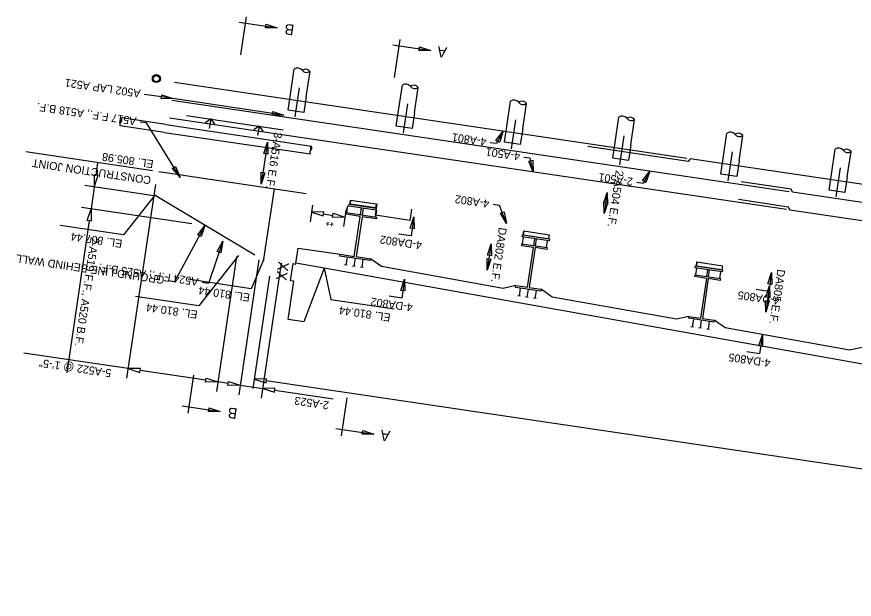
# Model space of a CAD drawing. Extents: x 1468952 to 1470054, y 573916 to 574214.
# Drawn here: x 1468962.4 to 1469014.8, y 574056.5 to 574092.9 of the extents above; entities that cross this region are included whole.
import ezdxf

# ---------------------------------------------------------------- set-up
doc = ezdxf.new("R2010")
doc.units = 0
for name, color, linetype in [('BR_P_Beam_Object', 7, 'Continuous'), ('BR_P_Beam_Stl_Det', 7, 'Continuous'), ('BR_P_Gen_Centerline', 7, 'Continuous'), ('BR_P_Gen_Phase_Construction', 7, 'Continuous'), ('BR_P_Sub_Centerline', 7, 'Continuous'), ('BR_P_Sub_Deep_Centerline', 7, 'Continuous'), ('BR_P_Sub_Foot_Centerline', 7, 'Continuous'), ('BR_P_Sub_Foot_Hidden', 7, 'Continuous'), ('BR_X_SV_Beam_Seat', 7, 'Continuous'), ('Default', 7, 'Continuous'), ('GE_P_CL_50', 7, 'Continuous'), ('GK_Cells', 7, 'Continuous'), ('PF_X_Ground_Line', 7, 'Continuous'), ('PV_X_EOP', 7, 'Continuous'), ('SV_X_Text_Elevation', 7, 'Continuous'), ('UT_X_Water', 7, 'Continuous')]:
    doc.layers.add(name, color=color, linetype=linetype)

# ---------------------------------------------------------------- blocks, each defined once
blk = doc.blocks.new('arrowOhio')
at = {"layer": 'Default'}
blk.add_lwpolyline([(0.00381, 0.000635), (0.00381, -0.000635), (0, 0)], close=True, dxfattribs=at)

msp = doc.modelspace()

# ---------------------------------------------------------------- linework, layer by layer
at = {"layer": 'BR_P_Beam_Object'}
for p, q in [((1468971.669, 574085.68), (1468980.77, 574084.333)), ((1468971.743, 574086.174), (1468980.843, 574084.827)), ((1468977.303, 574077.995), (1468971.084, 574081.728))]:
    msp.add_line(p, q, dxfattribs=at)
for centre, start, end in [((1468980.955, 574084.684), 127.976, 215.1816), ((1468980.695, 574084.723), 307.976, 35.1816), ((1468980.918, 574084.437), 127.976, 215.1816)]:
    msp.add_arc(centre, 0.181, start, end, dxfattribs=at)
at = {"layer": 'BR_P_Beam_Stl_Det'}
for p, q in [((1468976.329, 574092.572), (1468978.703, 574092.22)), ((1468976.432, 574090.535), (1468976.783, 574092.909)), ((1468986.025, 574089.115), (1468986.377, 574091.489)), ((1468985.922, 574091.152), (1468988.296, 574090.8)), ((1469004.297, 574084.051), (1468972.298, 574088.788)), ((1469010.688, 574081.967), (1468972.133, 574087.675)), ((1469010.523, 574080.854), (1468971.968, 574086.562)), ((1468973.468, 574070.513), (1468973.116, 574068.139)), ((1468983.061, 574069.093), (1468982.709, 574066.719)), ((1468972.779, 574068.593), (1468975.153, 574068.242)), ((1468982.372, 574067.173), (1468984.746, 574066.821))]:
    msp.add_line(p, q, dxfattribs=at)
for points in [[(1469030.229, 574080.212), (1469004.495, 574084.021), (1469004.371, 574083.865), (1468998.106, 574084.792)], [(1469046.308, 574076.694), (1469010.886, 574081.938), (1469010.812, 574082.124), (1469007.68, 574082.588)], [(1469046.144, 574075.581), (1469010.721, 574080.825), (1469010.648, 574081.011), (1469007.515, 574081.475)]]:
    msp.add_lwpolyline(points, dxfattribs=at)
at = {"layer": 'BR_P_Gen_Centerline'}
for p, q in [((1468971.743, 574086.174), (1468968.973, 574086.585)), ((1468971.669, 574085.68), (1468968.9, 574086.09))]:
    msp.add_line(p, q, dxfattribs=at)
for radius in [0.25, 0.2]:
    msp.add_circle((1468971.156, 574089.041), radius, dxfattribs=at)
for centre, start, end in [((1468969.048, 574086.194), 127.976, 215.1816), ((1468969.084, 574086.442), 127.976, 215.1816), ((1468968.825, 574086.48), 307.976, 35.1816)]:
    msp.add_arc(centre, 0.181, start, end, dxfattribs=at)
at = {"layer": 'BR_P_Gen_Phase_Construction'}
for p, q in [((1468979.531, 574088.054), (1468979.766, 574089.637)), ((1468980.52, 574087.908), (1468980.755, 574089.49)), ((1468986.291, 574087.053), (1468986.525, 574088.636)), ((1468987.28, 574086.907), (1468987.514, 574088.49)), ((1468993.051, 574086.053), (1468993.285, 574087.635)), ((1468994.04, 574085.906), (1468994.274, 574087.489)), ((1468999.81, 574085.052), (1469000.044, 574086.635)), ((1469000.799, 574084.905), (1469001.034, 574086.488)), ((1469006.57, 574084.051), (1469006.804, 574085.634)), ((1469007.559, 574083.905), (1469007.793, 574085.487)), ((1469013.329, 574083.05), (1469013.564, 574084.633)), ((1469014.319, 574082.904), (1469014.553, 574084.487))]:
    msp.add_line(p, q, dxfattribs=at)
for centre, start, end in [((1468979.974, 574089.341), 37.976, 125.1816), ((1468980.469, 574089.267), 37.976, 125.1816), ((1468980.546, 574089.787), 217.976, 305.1816), ((1468986.734, 574088.34), 37.976, 125.1816), ((1468987.229, 574088.267), 37.976, 125.1816), ((1468987.306, 574088.786), 217.976, 305.1816), ((1468993.494, 574087.339), 37.976, 125.1816), ((1468993.988, 574087.266), 37.976, 125.1816), ((1468994.065, 574087.785), 217.976, 305.1816), ((1469000.253, 574086.338), 37.976, 125.1816), ((1469000.748, 574086.265), 37.976, 125.1816), ((1469000.825, 574086.784), 217.976, 305.1816), ((1469007.013, 574085.338), 37.976, 125.1816), ((1469007.508, 574085.264), 37.976, 125.1816), ((1469007.584, 574085.784), 217.976, 305.1816), ((1469013.773, 574084.337), 37.976, 125.1816), ((1469014.267, 574084.264), 37.976, 125.1816), ((1469014.344, 574084.783), 217.976, 305.1816)]:
    msp.add_arc(centre, 0.362, start, end, dxfattribs=at)
at = {"layer": 'BR_P_Sub_Centerline'}
for p, q in [((1468979.385, 574087.065), (1468979.531, 574088.054)), ((1468980.52, 574087.908), (1468980.374, 574086.918)), ((1468980.374, 574086.918), (1468979.385, 574087.065)), ((1468986.144, 574086.064), (1468986.291, 574087.053)), ((1468987.28, 574086.907), (1468987.134, 574085.918)), ((1468987.134, 574085.918), (1468986.144, 574086.064)), ((1468992.904, 574085.063), (1468993.051, 574086.053)), ((1468994.04, 574085.906), (1468993.893, 574084.917)), ((1468993.893, 574084.917), (1468992.904, 574085.063)), ((1468999.664, 574084.063), (1468999.81, 574085.052)), ((1469000.799, 574084.905), (1469000.653, 574083.916)), ((1469000.653, 574083.916), (1468999.664, 574084.063)), ((1469006.423, 574083.062), (1469006.57, 574084.051)), ((1469007.559, 574083.905), (1469007.413, 574082.915)), ((1469007.413, 574082.915), (1469006.423, 574083.062)), ((1469013.183, 574082.061), (1469013.329, 574083.05)), ((1469014.319, 574082.904), (1469014.172, 574081.915)), ((1469014.172, 574081.915), (1469013.183, 574082.061))]:
    msp.add_line(p, q, dxfattribs=at)
at = {"layer": 'BR_P_Sub_Deep_Centerline'}
msp.add_line((1468977.874, 574077.746), (1468978.527, 574082.158), dxfattribs=at)
at = {"layer": 'BR_P_Sub_Foot_Centerline'}
for p, q in [((1468983.062, 574080.665), (1468983.124, 574081.087)), ((1468983.909, 574080.539), (1468983.972, 574080.962)), ((1468984.028, 574080.522), (1468984.091, 574080.944)), ((1468984.876, 574080.396), (1468984.938, 574080.819)), ((1468994.039, 574078.706), (1468994.102, 574079.129)), ((1468994.736, 574078.603), (1468994.799, 574079.025)), ((1468994.835, 574078.588), (1468994.898, 574079.011)), ((1468995.532, 574078.485), (1468995.595, 574078.908)), ((1469004.856, 574076.771), (1469004.919, 574077.194)), ((1469005.553, 574076.668), (1469005.616, 574077.09)), ((1469005.652, 574076.653), (1469005.715, 574077.076)), ((1469006.349, 574076.55), (1469006.412, 574076.973))]:
    msp.add_line(p, q, dxfattribs=at)
at = {"layer": 'BR_P_Sub_Foot_Hidden'}
msp.add_line((1468981.648, 574077.187), (1468979.871, 574077.508), dxfattribs=at)
at = {"layer": 'BR_X_SV_Beam_Seat'}
for p, q in [((1468973.039, 574086.741), (1468979.083, 574085.846)), ((1468974.55, 574086.517), (1468974.229, 574086.279)), ((1468974.55, 574086.517), (1468974.463, 574085.923)), ((1468974.55, 574086.517), (1468974.789, 574086.196)), ((1468977.572, 574086.07), (1468977.251, 574085.831)), ((1468977.572, 574086.07), (1468977.485, 574085.476)), ((1468977.572, 574086.07), (1468977.811, 574085.748)), ((1468970.91, 574083.285), (1468962.997, 574084.457))]:
    msp.add_line(p, q, dxfattribs=at)
msp.add_lwpolyline([(1468987.091, 574080.89), (1468986.986, 574080.179), (1468984.843, 574080.496), (1468984.948, 574081.207)], dxfattribs=at)
at = {"layer": 'GE_P_CL_50'}
for p, q in [((1468983.188, 574081.078), (1468983.206, 574081.202)), ((1468984.875, 574080.828), (1468983.188, 574081.078)), ((1468983.206, 574081.202), (1468984.893, 574080.952)), ((1468983.294, 574081.452), (1468983.256, 574081.194)), ((1468984.882, 574081.217), (1468984.843, 574080.959)), ((1468984.893, 574080.952), (1468984.875, 574080.828)), ((1468994.111, 574079.517), (1468994.073, 574079.259)), ((1468994.005, 574079.143), (1468994.023, 574079.267)), ((1468995.692, 574078.893), (1468994.005, 574079.143)), ((1468994.023, 574079.267), (1468995.71, 574079.017)), ((1468995.699, 574079.282), (1468995.66, 574079.024)), ((1468995.71, 574079.017), (1468995.692, 574078.893)), ((1469004.822, 574077.208), (1469004.84, 574077.332)), ((1469004.84, 574077.332), (1469006.527, 574077.082)), ((1469004.928, 574077.582), (1469004.89, 574077.324)), ((1469006.516, 574077.347), (1469006.477, 574077.089)), ((1469006.509, 574076.958), (1469004.822, 574077.208)), ((1469006.527, 574077.082), (1469006.509, 574076.958))]:
    msp.add_line(p, q, dxfattribs=at)
for points in [[(1468984.882, 574081.217), (1468984.843, 574080.959), (1468983.256, 574081.194), (1468983.294, 574081.452)], [(1468995.699, 574079.282), (1468995.66, 574079.024), (1468994.073, 574079.259), (1468994.111, 574079.517)], [(1469006.516, 574077.347), (1469006.477, 574077.089), (1469004.89, 574077.324), (1469004.928, 574077.582)]]:
    msp.add_lwpolyline(points, close=True, dxfattribs=at)
at = {"layer": 'GK_Cells'}
for p, q in [((1468983.004, 574080.558), (1468983.021, 574080.671)), ((1468983.892, 574080.426), (1468983.004, 574080.558)), ((1468983.021, 574080.671), (1468984.917, 574080.39)), ((1468983.523, 574077.932), (1468983.892, 574080.426)), ((1468984.012, 574080.408), (1468983.643, 574077.915)), ((1468984.9, 574080.277), (1468984.012, 574080.408)), ((1468984.917, 574080.39), (1468984.9, 574080.277)), ((1468993.981, 574078.599), (1468993.998, 574078.712)), ((1468994.719, 574078.49), (1468993.981, 574078.599)), ((1468993.998, 574078.712), (1468995.573, 574078.479)), ((1468994.35, 574075.996), (1468994.719, 574078.49)), ((1468994.819, 574078.475), (1468994.449, 574075.981)), ((1468995.557, 574078.366), (1468994.819, 574078.475)), ((1468995.573, 574078.479), (1468995.557, 574078.366)), ((1468982.618, 574077.951), (1468982.635, 574078.064)), ((1468984.514, 574077.67), (1468982.618, 574077.951)), ((1468982.635, 574078.064), (1468983.523, 574077.932)), ((1468983.071, 574077.884), (1468982.998, 574077.389)), ((1468983.566, 574077.81), (1468983.493, 574077.316)), ((1468983.643, 574077.915), (1468984.531, 574077.783)), ((1468983.081, 574077.377), (1468982.916, 574077.401)), ((1468983.575, 574077.303), (1468983.41, 574077.328)), ((1468984.061, 574077.737), (1468983.987, 574077.242)), ((1468984.531, 574077.783), (1468984.514, 574077.67)), ((1468984.07, 574077.23), (1468983.905, 574077.255)), ((1469004.798, 574076.664), (1469004.815, 574076.777)), ((1469004.815, 574076.777), (1469006.39, 574076.544)), ((1469005.536, 574076.555), (1469004.798, 574076.664)), ((1469005.167, 574074.061), (1469005.536, 574076.555)), ((1469005.636, 574076.54), (1469005.266, 574074.046)), ((1469006.374, 574076.431), (1469005.636, 574076.54)), ((1469006.39, 574076.544), (1469006.374, 574076.431)), ((1468993.595, 574075.992), (1468993.612, 574076.105)), ((1468995.171, 574075.759), (1468993.595, 574075.992)), ((1468993.612, 574076.105), (1468994.35, 574075.996)), ((1468993.888, 574075.948), (1468993.815, 574075.454)), ((1468994.383, 574075.875), (1468994.31, 574075.381)), ((1468994.449, 574075.981), (1468995.187, 574075.872)), ((1468994.878, 574075.802), (1468994.804, 574075.307)), ((1468995.187, 574075.872), (1468995.171, 574075.759)), ((1468993.898, 574075.442), (1468993.733, 574075.466)), ((1468994.392, 574075.368), (1468994.227, 574075.393)), ((1468994.887, 574075.295), (1468994.722, 574075.32)), ((1469004.412, 574074.057), (1469004.429, 574074.17)), ((1469004.429, 574074.17), (1469005.167, 574074.061)), ((1469005.988, 574073.824), (1469004.412, 574074.057)), ((1469004.705, 574074.013), (1469004.632, 574073.519)), ((1469005.2, 574073.94), (1469005.127, 574073.446)), ((1469005.266, 574074.046), (1469006.004, 574073.937)), ((1469005.695, 574073.867), (1469005.621, 574073.372)), ((1469006.004, 574073.937), (1469005.988, 574073.824)), ((1469004.715, 574073.507), (1469004.55, 574073.531)), ((1469005.209, 574073.433), (1469005.044, 574073.458)), ((1469005.704, 574073.36), (1469005.539, 574073.385))]:
    msp.add_line(p, q, dxfattribs=at)
at = {"layer": 'PF_X_Ground_Line'}
for p, q in [((1468979.871, 574077.508), (1468980.011, 574078.452)), ((1468980.011, 574078.452), (1468982.795, 574078.04)), ((1468979.539, 574076.404), (1468979.698, 574077.476)), ((1468979.698, 574077.476), (1468979.862, 574077.451)), ((1468981.648, 574077.187), (1468980.376, 574073.837)), ((1468981.648, 574077.187), (1468981.648, 574077.187)), ((1468981.648, 574077.187), (1468981.648, 574077.187)), ((1469026.696, 574069.14), (1468981.648, 574077.187)), ((1468979.383, 574073.984), (1468979.737, 574076.375)), ((1468979.737, 574076.375), (1468979.539, 574076.404)), ((1468980.376, 574073.837), (1468979.383, 574073.984))]:
    msp.add_line(p, q, dxfattribs=at)
for points in [[(1468993.612, 574076.105), (1468992.828, 574075.93), (1468985.216, 574077.29), (1468984.531, 574077.783)], [(1469004.429, 574074.17), (1469003.646, 574073.998), (1468995.874, 574075.386), (1468995.187, 574075.872)], [(1469015.246, 574072.235), (1469014.463, 574072.066), (1469006.691, 574073.454), (1469006.004, 574073.937)]]:
    msp.add_lwpolyline(points, dxfattribs=at)
at = {"layer": 'PV_X_EOP'}
msp.add_line((1468971.306, 574083.227), (1468980.516, 574081.863), dxfattribs=at)
at = {"layer": 'SV_X_Text_Elevation'}
for p, q in [((1468971.195, 574087.94), (1468970.404, 574088.057)), ((1468972.193, 574087.793), (1468971.195, 574087.94)), ((1468972.193, 574087.793), (1468972.193, 574087.793)), ((1468979.13, 574086.766), (1468972.193, 574087.793)), ((1468970.539, 574086.269), (1468970.143, 574086.328)), ((1468972.634, 574082.862), (1468970.539, 574086.269)), ((1468992.826, 574085.749), (1468992.407, 574084.975)), ((1468978.099, 574085.065), (1468977.711, 574082.447)), ((1468992.407, 574084.975), (1468992.011, 574085.034)), ((1468994.515, 574084.06), (1468994.12, 574084.119)), ((1468967.389, 574083.016), (1468967.501, 574083.768)), ((1468994.692, 574083.198), (1468994.515, 574084.06)), ((1469001.981, 574083.256), (1469001.562, 574082.482)), ((1469001.562, 574082.482), (1469001.166, 574082.541)), ((1468970.997, 574081.713), (1468966.684, 574082.352)), ((1468967.278, 574082.264), (1468967.076, 574080.903)), ((1468971.094, 574082.427), (1468969.301, 574070.321)), ((1468971.092, 574081.782), (1468969.104, 574079.275)), ((1468999.326, 574081.922), (1468999.132, 574080.613)), ((1468973.38, 574079.97), (1468966.483, 574080.991)), ((1468980.911, 574081.123), (1468980.76, 574080.099)), ((1468992.59, 574081.104), (1468992.194, 574081.163)), ((1468993.031, 574079.988), (1468992.59, 574081.104)), ((1468981.599, 574080.581), (1468982.179, 574080.495)), ((1468983.008, 574080.902), (1468982.843, 574079.79)), ((1468966.965, 574080.151), (1468965.56, 574070.66)), ((1468987.241, 574080.393), (1468987.065, 574079.206)), ((1468969.104, 574079.275), (1468965.147, 574079.861)), ((1468974.193, 574079.862), (1468972.29, 574076.344)), ((1468975.301, 574078.886), (1468974.417, 574076.229)), ((1468987.065, 574079.206), (1468986.274, 574079.323)), ((1468992.073, 574078.713), (1468991.828, 574077.058)), ((1468976.289, 574077.98), (1468973.804, 574074.846)), ((1468976.156, 574077.926), (1468974.907, 574069.491)), ((1468977.557, 574077.718), (1468976.308, 574069.284)), ((1468977.874, 574077.746), (1468977.079, 574075.91)), ((1468978.958, 574077.511), (1468977.71, 574069.076)), ((1468981.648, 574077.187), (1468982.05, 574075.228)), ((1469009.588, 574076.921), (1469009.413, 574075.734)), ((1468972.29, 574076.344), (1468971.894, 574076.402)), ((1468977.079, 574075.91), (1468973.122, 574076.496)), ((1468974.417, 574076.229), (1468974.021, 574076.288)), ((1468978.226, 574076.7), (1468977.186, 574069.669)), ((1468986.665, 574076.507), (1468986.49, 574075.32)), ((1469009.413, 574075.734), (1469008.621, 574075.851)), ((1469009.466, 574076.094), (1469009.221, 574074.439)), ((1468973.804, 574074.846), (1468969.847, 574075.432)), ((1468982.05, 574075.228), (1468986.007, 574074.642)), ((1468986.49, 574075.32), (1468985.698, 574075.437)), ((1469009.013, 574073.035), (1469008.837, 574071.848)), ((1468969.389, 574070.915), (1468962.882, 574071.878)), ((1469008.837, 574071.848), (1469008.046, 574071.965)), ((1468974.243, 574070.196), (1468970.141, 574070.803)), ((1468975.644, 574069.989), (1468974.893, 574070.1)), ((1469070.259, 574056.497), (1468978.025, 574070.152)), ((1468976.396, 574069.877), (1468977.798, 574069.67)), ((1468978.549, 574069.559), (1468982.202, 574069.018))]:
    msp.add_line(p, q, dxfattribs=at)
for points in [[(1468967.515, 574082.997), (1468967.264, 574083.034), (1468967.278, 574082.264)], [(1468967.09, 574080.133), (1468966.84, 574080.17), (1468967.076, 574080.903)], [(1468981.581, 574080.456), (1468981.618, 574080.706), (1468980.848, 574080.692)], [(1468982.161, 574080.37), (1468982.198, 574080.621), (1468982.931, 574080.384)], [(1468970.123, 574070.678), (1468970.16, 574070.929), (1468969.389, 574070.915)], [(1468974.224, 574070.071), (1468974.262, 574070.321), (1468974.995, 574070.085)], [(1468975.626, 574069.863), (1468975.663, 574070.114), (1468976.396, 574069.877)], [(1468978.007, 574070.026), (1468978.044, 574070.277), (1468977.273, 574070.263)], [(1468978.531, 574069.433), (1468978.568, 574069.684), (1468977.798, 574069.67)]]:
    msp.add_lwpolyline(points, close=True, dxfattribs=at)
at = {"layer": 'UT_X_Water'}
for p, q in [((1468979.831, 574086.662), (1468980.099, 574088.475)), ((1468986.59, 574085.661), (1468986.859, 574087.475)), ((1468993.35, 574084.66), (1468993.618, 574086.474)), ((1469000.11, 574083.66), (1469000.378, 574085.473)), ((1469006.869, 574082.659), (1469007.138, 574084.473)), ((1469013.629, 574081.658), (1469013.897, 574083.472))]:
    msp.add_line(p, q, dxfattribs=at)

# ---------------------------------------------------------------- block references
at = {"layer": 'BR_P_Beam_Stl_Det', "xscale": 188.97600000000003, "yscale": 188.97599999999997, "rotation": 171.57876932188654}
for p in [(1468978.703, 574092.22), (1468988.296, 574090.8), (1468975.153, 574068.242), (1468984.746, 574066.821)]:
    msp.add_blockref('arrowOhio', p, dxfattribs=at)
at = {"layer": 'SV_X_Text_Elevation'}
for p, xscale, yscale, rotation in [((1468972.193, 574087.793), 191.49568000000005, 191.49568, 171.57876932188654), ((1468979.13, 574086.766), 191.49568000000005, 191.49568, 171.57876932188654), ((1468992.826, 574085.749), 191.49567999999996, 191.49568, -118.42123067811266), ((1468978.099, 574085.065), 191.49568000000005, 191.49568, -98.42123067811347), ((1468994.692, 574083.198), 191.49567999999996, 191.49568, 101.57876932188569), ((1468972.634, 574082.862), 191.49568, 191.49568, 121.57876932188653), ((1468977.711, 574082.447), 191.49568000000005, 191.49568, 81.57876932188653), ((1469001.981, 574083.256), 191.49567999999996, 191.49568, -118.42123067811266), ((1468999.326, 574081.922), 191.49568000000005, 191.49568, -98.42123067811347), ((1468999.132, 574080.613), 191.49568000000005, 191.49568, 81.57876932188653), ((1468993.031, 574079.988), 191.49568000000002, 191.49568000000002, 111.57876932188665), ((1468974.193, 574079.862), 191.49568000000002, 191.49567999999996, -118.42123067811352), ((1468987.241, 574080.393), 191.49568000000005, 191.49568, -98.42123067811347), ((1468975.301, 574078.886), 191.49568000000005, 191.49568000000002, -108.42123067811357), ((1468992.073, 574078.713), 191.49568000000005, 191.49568, -98.42123067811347), ((1468991.828, 574077.058), 191.49568000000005, 191.49568, 81.57876932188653), ((1469009.588, 574076.921), 191.49568000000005, 191.49568, -98.42123067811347), ((1468986.665, 574076.507), 191.49568000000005, 191.49568, -98.42123067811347), ((1469009.466, 574076.094), 191.49568000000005, 191.49568, -98.42123067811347), ((1469009.221, 574074.439), 191.49568000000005, 191.49568, 81.57876932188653), ((1469009.013, 574073.035), 191.49568000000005, 191.49568, -98.42123067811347)]:
    msp.add_blockref('arrowOhio', p, dxfattribs=dict(at, xscale=xscale, yscale=yscale, rotation=rotation))

# ---------------------------------------------------------------- texts
for s, height, rotation, p in [('B', 0.665, 171.5788, (1468979.802, 574092.394)), ('A', 0.665, 171.5788, (1468989.341, 574090.981)), ('A502 LAP A521', 0.5, 171.5788, (1468970.193, 574088.341)), ('A517 F.F., A518 B.F.', 0.5, 171.5788, (1468969.933, 574086.612)), ('3-A516 E.F.', 0.5, 261.5788, (1468978.524, 574085.715)), ('4-A801', 0.5, 171.5788, (1468991.8, 574085.318)), ('4-A501', 0.5, 171.5788, (1468993.909, 574084.403)), ('EL. 805.98', 0.5, 171.5788, (1468971.006, 574083.932)), ('CONSTRUCTION JOINT', 0.5, 171.5788, (1468970.857, 574082.923)), ('2-A501', 0.5, 171.5788, (1469000.956, 574082.825)), ('2-A504 E.F.', 0.5, 261.5788, (1468999.864, 574083.332)), ('4-A802', 0.5, 171.5788, (1468991.983, 574081.447)), ('**', 0.5, 171.5788, (1468982.301, 574080.275)), ('EL. 807.44', 0.5, 171.5788, (1468969.056, 574078.953)), ('DA802 E.F.', 0.5, 261.5788, (1468992.558, 574079.763)), ('2-A519 F.F., A520 B.F.', 0.5, 261.5788, (1468967.062, 574079.157)), ('4-DA802', 0.5, 171.5788, (1468987.774, 574078.853)), ('GROUND LINE BEHIND WALL', 0.5, 171.5788, (1468971.683, 574076.686)), ('A524 F.F., A525 B.F.', 0.5, 171.5788, (1468973.81, 574076.572)), ('XX', 0.665, 261.5788, (1468978.792, 574077.644)), ('DA805 E.F.', 0.5, 261.5788, (1469009.951, 574077.148)), ('EL. 810.44', 0.5, 171.5788, (1468977.031, 574075.588)), ('4-DA805', 0.5, 171.5788, (1469010.126, 574075.38)), ('4-DA802', 0.5, 171.5788, (1468987.199, 574074.966)), ('EL. 810.44', 0.5, 171.5788, (1468973.756, 574074.524)), ('EL. 810.44', 0.5, 171.5788, (1468985.813, 574074.341)), ('4-DA805', 0.5, 171.5788, (1469009.55, 574071.494)), ('5-A522 @ 1\'-5"', 0.5, 171.5788, (1468968.371, 574070.863)), ('2-A523', 0.5, 171.5788, (1468981.963, 574068.851)), ('B', 0.665, 171.5788, (1468976.252, 574068.415)), ('A', 0.665, 171.5788, (1468985.791, 574067.003))]:
    msp.add_text(s, height=height, rotation=rotation, dxfattribs=at).set_placement(p)

doc.saveas('drawing.dxf')
